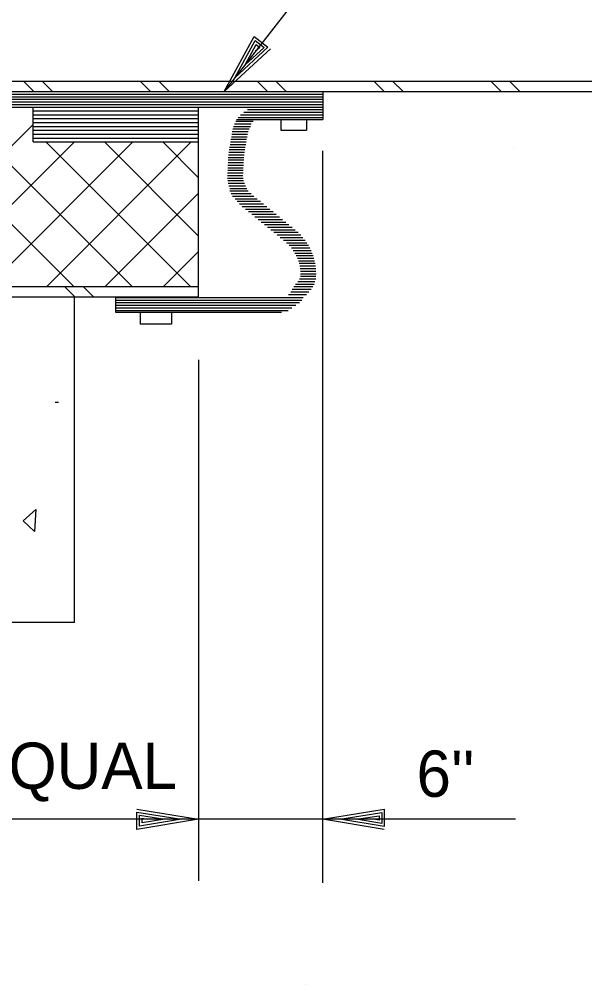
# Model space of a CAD drawing. Extents: x 22339.2 to 22413.4, y 22369.6 to 22418.8.
# Drawn here: x 22346.729 to 22349.01, y 22392.768 to 22396.66 of the extents above; entities that cross this region are included whole.
import ezdxf

# ---------------------------------------------------------------- set-up
doc = ezdxf.new("R2010")
doc.units = 0
for name, color, linetype in [('Level 1', 7, 'Continuous'), ('Level 2', 7, 'Continuous'), ('Level 4', 7, 'Continuous'), ('Level 44', 7, 'Continuous'), ('Level 7', 7, 'Continuous'), ('Level 8', 7, 'Continuous')]:
    doc.layers.add(name, color=color, linetype=linetype)

msp = doc.modelspace()

# ---------------------------------------------------------------- linework, layer by layer
at = {"layer": 'Level 1'}
for p, q in [((22346.7857, 22396.2906), (22347.4524, 22396.2906)), ((22347.4524, 22395.5406), (22347.4524, 22396.3063)), ((22346.7857, 22396.275), (22347.4524, 22396.275)), ((22346.7857, 22396.2594), (22347.4524, 22396.2594)), ((22347.784, 22396.2566), (22347.784, 22396.2136)), ((22347.8876, 22396.2566), (22347.8876, 22396.2136)), ((22346.7857, 22396.2438), (22347.4524, 22396.2438)), ((22346.7857, 22396.2281), (22347.4524, 22396.2281)), ((22346.7857, 22396.2125), (22347.4524, 22396.2125)), ((22347.784, 22396.2136), (22347.8876, 22396.2136)), ((22346.7857, 22396.1969), (22347.4524, 22396.1969)), ((22346.7857, 22396.1813), (22347.4524, 22396.1813)), ((22348.7215, 22396.1426), (22348.7215, 22396.1426)), ((22347.9524, 22396.1295), (22347.9524, 22393.1793)), ((22345.9524, 22395.5823), (22347.4524, 22395.5823)), ((22345.9524, 22395.5406), (22347.4524, 22395.5406)), ((22347.2162, 22395.479), (22347.2162, 22395.4313)), ((22347.3436, 22395.479), (22347.3436, 22395.4313)), ((22347.3436, 22395.4313), (22347.2162, 22395.4313)), ((22347.4524, 22395.2876), (22347.4524, 22393.1868)), ((22347.4524, 22393.4347), (22345.9524, 22393.4347)), ((22347.3831, 22393.4347), (22347.3831, 22393.4347)), ((22347.4524, 22393.4347), (22347.4524, 22393.4347)), ((22347.9524, 22393.4347), (22347.4524, 22393.4347)), ((22348.7312, 22393.4347), (22347.9524, 22393.4347)), ((22347.8831, 22392.768), (22347.8831, 22392.768))]:
    msp.add_line(p, q, dxfattribs=at)
at = {"layer": 'Level 2'}
for p, q in [((22348.6768, 22397.81), (22347.5563, 22396.3688)), ((22345.9524, 22396.4104), (22352.6356, 22396.4104)), ((22345.9524, 22396.3688), (22352.6121, 22396.3688)), ((22347.9537, 22396.3688), (22347.9537, 22396.2566)), ((22347.9537, 22396.3688), (22347.9537, 22396.3063)), ((22345.9524, 22396.3583), (22347.9537, 22396.3583)), ((22345.9524, 22396.3479), (22347.9537, 22396.3479)), ((22345.9524, 22396.3375), (22347.9537, 22396.3375)), ((22345.9524, 22396.3271), (22347.9537, 22396.3271)), ((22345.9524, 22396.3167), (22347.9537, 22396.3167)), ((22345.9524, 22396.3063), (22347.9537, 22396.3063)), ((22346.7857, 22396.1656), (22346.7857, 22396.3063)), ((22347.4524, 22396.1656), (22347.4524, 22396.3063)), ((22347.9537, 22396.3063), (22347.9537, 22396.2566)), ((22347.6056, 22396.2566), (22347.9537, 22396.2566)), ((22346.7857, 22396.1656), (22347.4524, 22396.1656)), ((22347.1179, 22395.5406), (22347.1179, 22395.479)), ((22347.1179, 22395.479), (22347.7874, 22395.479))]:
    msp.add_line(p, q, dxfattribs=at)
for points in [[(22347.742, 22396.5402), (22347.5563, 22396.3688), (22347.6767, 22396.591), (22347.7325, 22396.5476), (22347.5989, 22396.4235), (22347.6807, 22396.5744), (22347.7165, 22396.5465), (22347.6398, 22396.4761), (22347.6847, 22396.5578), (22347.6994, 22396.5463), (22347.6824, 22396.5309)], [(22347.65, 22396.2958), (22347.9524, 22396.2958)], [(22347.6704, 22396.3063), (22347.9537, 22396.3063)], [(22347.6024, 22396.249), (22347.6721, 22396.249)], [(22347.6119, 22396.2646), (22347.9524, 22396.2646)], [(22347.6222, 22396.275), (22347.9524, 22396.275)], [(22347.6346, 22396.2854), (22347.9524, 22396.2854)], [(22347.591, 22396.2177), (22347.6561, 22396.2177)], [(22347.5937, 22396.2281), (22347.6624, 22396.2281)], [(22347.5971, 22396.2386), (22347.664, 22396.2386)], [(22347.583, 22396.1761), (22347.6464, 22396.1761)], [(22347.5848, 22396.1865), (22347.6482, 22396.1865)], [(22347.5865, 22396.1969), (22347.6504, 22396.1969)], [(22347.5885, 22396.2073), (22347.6529, 22396.2073)], [(22347.5759, 22396.1344), (22347.6392, 22396.1344)], [(22347.5775, 22396.1448), (22347.641, 22396.1448)], [(22347.5794, 22396.1552), (22347.6429, 22396.1552)], [(22347.5812, 22396.1656), (22347.6447, 22396.1656)], [(22347.5718, 22396.0927), (22347.6344, 22396.0927)], [(22347.5724, 22396.1031), (22347.635, 22396.1031)], [(22347.5731, 22396.1136), (22347.6361, 22396.1136)], [(22347.5743, 22396.124), (22347.6375, 22396.124)], [(22347.5701, 22396.0615), (22347.6327, 22396.0615)], [(22347.5706, 22396.0719), (22347.6332, 22396.0719)], [(22347.5712, 22396.0823), (22347.6338, 22396.0823)], [(22347.5689, 22396.0302), (22347.6314, 22396.0302)], [(22347.5691, 22396.0406), (22347.6317, 22396.0406)], [(22347.5694, 22396.0198), (22347.6322, 22396.0198)], [(22347.5699, 22396.0511), (22347.633, 22396.0511)], [(22347.5706, 22396.0094), (22347.6341, 22396.0094)], [(22347.5724, 22395.999), (22347.6371, 22395.999)], [(22347.575, 22395.9886), (22347.6414, 22395.9886)], [(22347.5782, 22395.9781), (22347.647, 22395.9781)], [(22347.5782, 22395.9677), (22347.6531, 22395.9677)], [(22347.5833, 22395.9573), (22347.6645, 22395.9573)], [(22347.5897, 22395.9469), (22347.6759, 22395.9469)], [(22347.5997, 22395.9365), (22347.6892, 22395.9365)], [(22347.6078, 22395.9261), (22347.7019, 22395.9261)], [(22347.6173, 22395.9156), (22347.7147, 22395.9156)], [(22347.6286, 22395.9052), (22347.7275, 22395.9052)], [(22347.6414, 22395.8948), (22347.7402, 22395.8948)], [(22347.6541, 22395.8844), (22347.753, 22395.8844)], [(22347.6669, 22395.874), (22347.7658, 22395.874)], [(22347.6797, 22395.8636), (22347.7785, 22395.8636)], [(22347.6924, 22395.8531), (22347.7913, 22395.8531)], [(22347.7052, 22395.8427), (22347.804, 22395.8427)], [(22347.718, 22395.8323), (22347.8168, 22395.8323)], [(22347.7307, 22395.8219), (22347.8296, 22395.8219)], [(22347.7435, 22395.8115), (22347.8423, 22395.8115)], [(22347.7563, 22395.8011), (22347.8542, 22395.8011)], [(22347.769, 22395.7906), (22347.8646, 22395.7906)], [(22347.7818, 22395.7802), (22347.8737, 22395.7802)], [(22347.7946, 22395.7698), (22347.8818, 22395.7698)], [(22347.8071, 22395.7594), (22347.889, 22395.7594)], [(22347.8179, 22395.749), (22347.8954, 22395.749)], [(22347.827, 22395.7386), (22347.9011, 22395.7386)], [(22347.8347, 22395.7281), (22347.9061, 22395.7281)], [(22347.8413, 22395.7177), (22347.9104, 22395.7177)], [(22347.8468, 22395.7073), (22347.9142, 22395.7073)], [(22347.8515, 22395.6969), (22347.9175, 22395.6969)], [(22347.8553, 22395.6865), (22347.9201, 22395.6865)], [(22347.8583, 22395.6761), (22347.9223, 22395.6761)], [(22347.8607, 22395.6656), (22347.924, 22395.6656)], [(22347.8624, 22395.6552), (22347.9252, 22395.6552)], [(22347.8633, 22395.6448), (22347.9259, 22395.6448)], [(22347.8637, 22395.6344), (22347.9262, 22395.6344)], [(22347.8433, 22395.5927), (22347.9188, 22395.5927)], [(22347.853, 22395.6031), (22347.9214, 22395.6031)], [(22347.8602, 22395.6136), (22347.9252, 22395.6136)], [(22347.8633, 22395.624), (22347.9259, 22395.624)], [(22347.815, 22395.5511), (22347.8872, 22395.5511)], [(22347.824, 22395.5615), (22347.8975, 22395.5615)], [(22347.8298, 22395.5719), (22347.9066, 22395.5719)], [(22347.8362, 22395.5823), (22347.913, 22395.5823)], [(22347.1191, 22395.5384), (22347.875, 22395.5384)], [(22347.1191, 22395.528), (22347.8685, 22395.528)], [(22347.1191, 22395.5176), (22347.8599, 22395.5176)], [(22347.1191, 22395.5072), (22347.8447, 22395.5072)], [(22347.1191, 22395.4968), (22347.8289, 22395.4968)], [(22347.1191, 22395.4864), (22347.8136, 22395.4864)], [(22347.2031, 22393.476), (22347.4524, 22393.4347), (22347.2031, 22393.3933), (22347.2031, 22393.464), (22347.3831, 22393.4347), (22347.2137, 22393.4067), (22347.2137, 22393.452), (22347.3164, 22393.4347), (22347.2244, 22393.42), (22347.2244, 22393.4387), (22347.2471, 22393.4347)], [(22348.2017, 22393.3933), (22347.9524, 22393.4347), (22348.2017, 22393.476), (22348.2017, 22393.4053), (22348.0217, 22393.4347), (22348.1911, 22393.4627), (22348.1911, 22393.4173), (22348.0884, 22393.4347), (22348.1804, 22393.4493), (22348.1804, 22393.4307), (22348.1577, 22393.4347)]]:
    msp.add_lwpolyline(points, dxfattribs=at)
at = {"layer": 'Level 44'}
msp.add_line((22346.8872, 22395.1152), (22346.8744, 22395.1152), dxfattribs=at)
msp.add_lwpolyline([(22346.7912, 22394.5952), (22346.7449, 22394.638), (22346.7962, 22394.6837)], close=True, dxfattribs=at)
at = {"layer": 'Level 7'}
for q in [(22346.9524, 22395.5406), (22345.5149, 22394.2281)]:
    msp.add_line((22346.9524, 22394.2281), q, dxfattribs=at)
at = {"layer": 'Level 8'}
for p, q in [((22347.5989, 22396.4235), (22347.5989, 22396.4235)), ((22347.5563, 22396.3688), (22347.5563, 22396.3688)), ((22347.3831, 22393.4347), (22347.3831, 22393.4347)), ((22347.4524, 22393.4347), (22347.4524, 22393.4347)), ((22347.9524, 22393.4347), (22347.9524, 22393.4347)), ((22348.0217, 22393.4347), (22348.0217, 22393.4347))]:
    msp.add_line(p, q, dxfattribs=at)
for points in [[(22346.7874, 22396.3688), (22346.7458, 22396.4104)], [(22346.8629, 22396.3688), (22346.8212, 22396.4104)], [(22347.2588, 22396.3688), (22347.2172, 22396.4104)], [(22347.3343, 22396.3688), (22347.2926, 22396.4104)], [(22347.7302, 22396.3688), (22347.6886, 22396.4104)], [(22347.8057, 22396.3688), (22347.764, 22396.4104)], [(22348.2016, 22396.3688), (22348.16, 22396.4104)], [(22348.2771, 22396.3688), (22348.2354, 22396.4104)], [(22348.673, 22396.3688), (22348.6314, 22396.4104)], [(22348.7485, 22396.3688), (22348.7068, 22396.4104)], [(22346.9487, 22395.5823), (22346.2247, 22396.3063)], [(22347.1844, 22395.5823), (22346.4604, 22396.3063)], [(22346.1328, 22395.5823), (22346.7857, 22396.2352)], [(22346.3685, 22395.5823), (22346.9518, 22396.1656)], [(22346.6042, 22395.5823), (22347.1875, 22396.1656)], [(22347.4201, 22395.5823), (22346.8367, 22396.1656)], [(22346.8399, 22395.5823), (22347.4232, 22396.1656)], [(22347.4524, 22395.7857), (22347.0724, 22396.1656)], [(22347.4524, 22396.0214), (22347.3081, 22396.1656)], [(22347.0756, 22395.5823), (22347.4524, 22395.9591)], [(22347.3113, 22395.5823), (22347.4524, 22395.7234)], [(22346.9538, 22395.5406), (22346.9121, 22395.5823)], [(22347.0292, 22395.5406), (22346.9875, 22395.5823)]]:
    msp.add_lwpolyline(points, dxfattribs=at)

# ---------------------------------------------------------------- texts
at = {"layer": 'Level 4'}
for s, p in [('EQUAL', (22346.5193, 22393.5573)), ("6''", (22348.3317, 22393.5254))]:
    msp.add_text(s, height=0.18667, dxfattribs=at).set_placement(p)

doc.saveas('drawing.dxf')
